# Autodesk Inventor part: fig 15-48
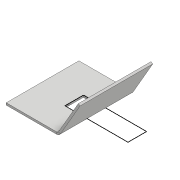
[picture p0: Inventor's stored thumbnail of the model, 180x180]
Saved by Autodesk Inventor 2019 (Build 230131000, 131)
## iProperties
Created: 2015-07
Part Number: fig 15-48
Material: Generic
Document SubType Name: Sheet Metal
Designer: Sandeep
Density: 1 g/cm^3
Sheet Metal Rule: Default_mm
Appearance: Default
Author: Sandeep
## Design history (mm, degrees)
node "Face1"
  sketch "Sketch1"
    geometry: L1 (-12.609, 8.313)-(0, 8.313); L2 (0, 8.313)-(0, -9.006); L3 (0, -9.006)-(-12.609, -9.006); L4 (-12.609, -9.006)-(-12.609, 8.313); 1 further point
    constraints: 8 end point, 2 parallel, 1 horizontal, 1 perpendicular
node "Flange1"
sketch "Sketch3"
  geometry: L1 (9.998, 1.795)-(-5.034, 1.795); L2 (-5.034, 1.795)-(-5.034, -2.633); L3 (-5.034, -2.633)-(9.998, -2.633); L4 (9.998, -2.633)-(9.998, 1.795); 1 further point
  constraints: 8 end point, 2 parallel, 1 horizontal, 1 perpendicular
cut "Cut1" sketch "Sketch3" dims "d11" = 0.5 (= Thickness), "d12" = 0
body "Solid1"
face "Plate1" dims "d13" = 0.5 (= Thickness)
sketch "Sketch2"
  geometry: L1 through (-8.66, 0) direction (1, 0); L2 through (0, 5) direction (0, 1); L3 (0, 10)-(-17.319, 10); L4 (-17.319, 10)-(-17.319, 0)
  constraints: 6 end point, 1 horizontal, 1 perpendicular, 1 vertical
face "Plate2" dims "d1" = 0.5 (= BendReliefWidth), "d2" = 0.25 (= BendReliefDepth), "d3" = 1 (= MinimumRemnant), "d4" = 0.5 (= BendRadius), "d5" = 10, "d6" = 60 deg, "d7" = 0.5 (= BendRadius), "d8" = 2 (= CornerReliefSize), "d9" = 0.5 (= GapSize), "d10" = 0.5 (= JacobiRadiusSize), "d13" = 0.5 (= Thickness), "SeamGap" = 0.01
bend "Bend1" dims "d1" = 0.5 (= BendReliefWidth), "d2" = 0.25 (= BendReliefDepth), "d3" = 1 (= MinimumRemnant), "d4" = 0.5 (= BendRadius), "d5" = 10, "d6" = 60 deg, "d7" = 0.5 (= BendRadius), "d13" = 0.5 (= Thickness), "SeamGap" = 0.01
feature "Corner1" dims "d5" = 10, "d6" = 60 deg, "d8" = 2 (= CornerReliefSize), "d9" = 0.5 (= GapSize), "d10" = 0.5 (= JacobiRadiusSize)
other parameters: "Thickness" = 0.5, "BendRadius" = 0.5 (= Thickness), "BendReliefWidth" = 0.5 (= Thickness), "BendReliefDepth" = 0.25 (= 0.5 x Thickness), "CornerReliefSize" = 2 (= 4 x Thickness), "MinimumRemnant" = 1 (= 2 x Thickness), "TransitionRadius" = 0.5 (= BendRadius), "JacobiRadiusSize" = 0.5 (= BendRadius), "GapSize" = 0.5 (= Thickness), "d0" = 0.5 (= BendRadius)
